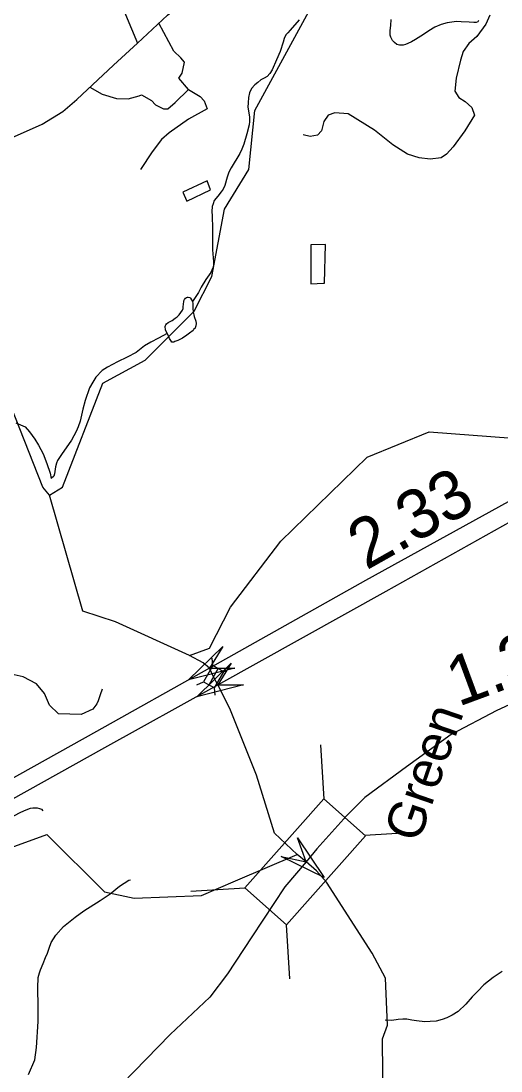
# Model space of a CAD drawing. Extents: x 2001466 to 31450019, y -30647475 to 847247.
# Drawn here: x 2190325 to 2192765, y 755901 to 761240 of the extents above; entities that cross this region are included whole.
import ezdxf

# ---------------------------------------------------------------- set-up
doc = ezdxf.new("R2010")
doc.units = 0
for name, color, linetype in [('Exist Hydrographic Creek Single Shore', 7, 'Continuous'), ('Exist Hydrographic Misc Water Feature', 7, 'Continuous'), ('Exist Road Non-System Type 51', 7, 'Continuous'), ('Exist Road Primary Interstate Structure Standard Bridge CELL', 7, 'Continuous'), ('Exist Road Primary US Divided Attributed', 7, 'Continuous'), ('Exist Road Primary US Mileage Hundredths English Label', 7, 'Continuous'), ('Exist Road Secondary Mileage Hundredths English Label', 7, 'Continuous'), ('Exist Road Secondary Structure Standard Bridge Attributed CELL', 7, 'Continuous'), ('Exist Road Secondary Structure Standard Bridge CELL', 7, 'Continuous'), ('Exist Road Secondary Type 51 Attributed', 7, 'Continuous'), ('Exist Road Secondary Type 51 Label', 7, 'Continuous')]:
    doc.layers.add(name, color=color, linetype=linetype)

msp = doc.modelspace()

# ---------------------------------------------------------------- linework, layer by layer
at = {"layer": 'Exist Hydrographic Creek Single Shore'}
for points in [[(2190469.9, 758829.2), (2190436.1, 758869.3), (2190249.9, 759342.2), (2190006.1, 759589.9), (2189744, 760189.1), (2189718.6, 760324.2), (2189687.9, 760377.7), (2189649.7, 760439.3), (2189491, 760637.1), (2189321, 761119.6), (2188915, 761967.6), (2188863.9, 762116.3), (2188570.9, 762457), (2188494, 762661.9), (2188148.9, 763220.1), (2188122.1, 763519.1), (2188062, 763651.6), (2187886, 763917.6)], [(2191181.7, 758013), (2190804.7, 758185.4), (2190639.9, 758238.5), (2190469.9, 758829.2)], [(2191729.5, 757001.5), (2191613.9, 757109.8), (2191522.8, 757405.9), (2191386.3, 757743.6), (2191325.6, 757864), (2191304.3, 757905.6), (2191282.4, 757949), (2191250.9, 757976.2), (2191181.7, 758013)], [(2185352.2, 756510.1), (2185629, 756570), (2185770.9, 756547.4), (2186303, 756582.4), (2186784.9, 756828.4), (2186910, 756829.1), (2187035.1, 756770.8), (2187169, 756646.6), (2187369.9, 756557.2), (2187911.1, 756562.5), (2188359.9, 756704.2), (2188925, 756951.8), (2189514, 757238.2), (2189606, 757229.8), (2189632.1, 757130.8), (2189775, 756855.6), (2190457, 757104.1), (2190750, 756812.6), (2190899.9, 756780), (2191241.9, 756792.7), (2191416, 756867.8), (2191729.5, 757001.5)], [(2192055.6, 754701.5), (2192091.6, 754785.1), (2192093.8, 754815.2), (2192088, 754889.1), (2192085.9, 755223.8), (2192166.9, 755533.8), (2192163, 756065.3), (2192188, 756133.7), (2192178, 756373.3), (2192109.9, 756499.4), (2191877.5, 756860.6), (2191826.2, 756918.6), (2191774.2, 756964.8), (2191729.5, 757001.5)]]:
    msp.add_lwpolyline(points, dxfattribs=at)
at = {"layer": 'Exist Hydrographic Misc Water Feature'}
for points in [[(2190469.9, 758829.2), (2190535.9, 758870.5), (2190741, 759397.7), (2190956.9, 759514.7), (2191205, 759765.4), (2191295, 759940.8), (2191359, 760283.8), (2191483.1, 760484.7), (2191514, 760785.8), (2191818.9, 761343.8), (2191840.9, 761651.7), (2192006, 762012.4), (2192146, 762206.4), (2192287.1, 762321.6), (2192478, 762406.2), (2192676.9, 762467.8), (2193190.9, 762919.7), (2193573, 763082.5), (2193722, 763181.1), (2193963, 763218.8), (2194113.1, 763284.6), (2194310.9, 763477.3), (2194694, 763604), (2194829.6, 763616.5)], [(2191181.7, 758013), (2191282.9, 758051.5), (2191390, 758259.2), (2191645.9, 758595.2), (2192083.9, 759022.4), (2192400.1, 759150.5), (2192824.9, 759118.8), (2193033.1, 759144), (2193431.9, 759355.6), (2193689, 759458.6), (2194255, 759620.8), (2194453, 759803.8), (2194794, 760000.2), (2194950.9, 760174.1), (2195089.9, 760509.1), (2195070.9, 760883.4), (2195144.9, 760967.2), (2195245, 761034), (2195426, 761276.3)], [(2191738.8, 761245.4), (2191693.2, 761193.5), (2191680.9, 761179.1), (2191671.3, 761169.2), (2191663.1, 761151), (2191657.6, 761133.1), (2191642, 761084.8), (2191624.3, 761042.9), (2191602.4, 760992.6), (2191590.5, 760972.5), (2191576.6, 760958.4), (2191560.6, 760948.6), (2191544.8, 760940.5), (2191529.2, 760928.2), (2191513.2, 760916), (2191497, 760896.2), (2191487, 760874.2), (2191481.6, 760851.9), (2191479.8, 760823.7), (2191477.5, 760801.8), (2191486.3, 760752.1), (2191485.9, 760729.9), (2191484.7, 760711.9), (2191472.8, 760666.2), (2191457.2, 760613.7), (2191447, 760587.7), (2191437.3, 760565.7), (2191393.9, 760493.5), (2191382.2, 760471.4), (2191372.3, 760445.3), (2191360.7, 760403.3), (2191352.4, 760385.4), (2191342.8, 760371), (2191324.8, 760349), (2191307.1, 760326.9), (2191301, 760310.8), (2191297.3, 760296.8), (2191295.7, 760270.7), (2191295.9, 760248.7), (2191298.3, 760185.1), (2191298.5, 760132.7), (2191299.1, 760077.1), (2191303.2, 760015.2), (2191303.4, 760000.9), (2191301.4, 759989.1), (2191295.2, 759973), (2191289.5, 759960.9), (2191263.9, 759925), (2191240.1, 759886.8), (2191226.5, 759860.4), (2191196.6, 759814.2)], [(2192650.6, 761241.9), (2192646.5, 761235.6), (2192638.7, 761232), (2192626.4, 761231.8), (2192602.4, 761233.4), (2192562.5, 761235.4), (2192538.5, 761236.9), (2192514.3, 761234.9), (2192490.7, 761230.8), (2192460.3, 761222.4), (2192428.8, 761208.5), (2192398.4, 761190), (2192370.7, 761171.8), (2192329.5, 761145.6), (2192309.2, 761133.7), (2192291.2, 761125.4), (2192279.1, 761121.2), (2192267.4, 761117.3), (2192257.5, 761117.1), (2192249.6, 761117.1), (2192241.8, 761119.1), (2192235.2, 761120.9), (2192223.3, 761130.8), (2192213.1, 761140.9), (2192205.5, 761158.7), (2192201.2, 761168.7), (2192201.2, 761178.8), (2192201, 761191), (2192204.4, 761216.8), (2192206.5, 761246.9)], [(2191288.9, 760380.8), (2191270.6, 760426.6), (2191146.8, 760369.8), (2191167.3, 760324.2), (2191288.9, 760380.8)], [(2191861.8, 759906.8), (2191867.7, 759906.7), (2191872.5, 760102.8), (2191798.2, 760102.2), (2191798, 759904.3), (2191861.8, 759906.8)], [(2191068, 759651.5), (2191059.4, 759669.5), (2191059.6, 759675.5), (2191057.8, 759681.5), (2191057.8, 759687.2), (2191059.8, 759691.3), (2191061.3, 759695.6), (2191065.4, 759699.4), (2191073.6, 759707.5), (2191093.5, 759717.5), (2191109.1, 759729.7), (2191119.5, 759735.9), (2191129.1, 759745.8), (2191137.1, 759757.9), (2191145.1, 759770.1), (2191149, 759778), (2191149, 759786.1), (2191152.9, 759814), (2191152.7, 759818), (2191156.6, 759823.9), (2191160.7, 759830.2), (2191166.5, 759834.2), (2191170.6, 759836), (2191174.5, 759836.3), (2191182.5, 759834.2), (2191186.6, 759830.4), (2191196.6, 759814.2)], [(2191196.6, 759814.2), (2191198.9, 759804.2), (2191199.1, 759780.2), (2191200.9, 759760.5), (2191205.2, 759738.3), (2191213.6, 759714.3), (2191215.5, 759702.7), (2191213.4, 759690.4), (2191211.2, 759684.6), (2191209.7, 759678.4), (2191203.6, 759672.4), (2191199.7, 759666.6), (2191181.6, 759652.2), (2191167.9, 759642.1), (2191146.2, 759628), (2191122, 759615.8), (2191106.2, 759609.7), (2191102.3, 759607.8), (2191098.2, 759607.7), (2191092.2, 759607.8), (2191086.3, 759615.5), (2191079.7, 759625.4), (2191074.2, 759639.7), (2191068, 759651.5)], [(2191068, 759651.5), (2191024, 759627.3), (2190984.2, 759607), (2190952.2, 759588.7), (2190910.8, 759554.4), (2190864.6, 759530.1), (2190815, 759507.6), (2190765.2, 759479.4), (2190737.5, 759463.3), (2190705.5, 759428.8), (2190689.5, 759402.9), (2190673.9, 759374.8), (2190650.4, 759310.6), (2190638.5, 759266.6), (2190625.1, 759204.5), (2190615.3, 759176.4), (2190605.4, 759152.3), (2190581.5, 759108.5), (2190554, 759070.1), (2190534.5, 759040.1), (2190510.5, 759006), (2190504.8, 758991.9), (2190500.5, 758973.8), (2190494.9, 758937.8), (2190491.2, 758925.8), (2190478.9, 758913.8)], [(2190299.1, 759196.6), (2190345.4, 759176.6)], [(2190345.4, 759176.6), (2190367.6, 759150.9), (2190395.7, 759113), (2190414.1, 759083), (2190438.3, 759039.2), (2190456.8, 758989.4), (2190473, 758941.5), (2190478.9, 758913.8)], [(2189622.6, 757068.1), (2189719.2, 756913.1), (2190042, 757069.3), (2190324.9, 757217.2), (2190350.8, 757229.5), (2190372.9, 757237.5), (2190384.8, 757239.7), (2190396.5, 757239.6), (2190406.7, 757239.7), (2190418.4, 757235.9), (2190428.9, 757231.9), (2190436.5, 757224.2)], [(2190363.9, 755884), (2190395.3, 755958.3), (2190403.1, 756020), (2190412.3, 756152.1), (2190411.7, 756228), (2190411.3, 756324.2), (2190412.7, 756375.9), (2190418.4, 756400.2), (2190424.4, 756416), (2190438.3, 756448.3), (2190450, 756478.2), (2190459.7, 756500.2), (2190467.4, 756526.3), (2190477.5, 756554.3), (2190501.3, 756592.5), (2190540.6, 756634.9), (2190600.7, 756683.4), (2190644.2, 756715.8), (2190727.9, 756768), (2190777.7, 756802.3), (2190825.3, 756840.9), (2190872.8, 756871.1), (2190880.8, 756873.1)], [(2192771.6, 756406.5), (2192725.7, 756376.1), (2192678.1, 756339.9), (2192646.3, 756307.4), (2192618.4, 756277.5), (2192586.9, 756240.9), (2192546.9, 756202.7), (2192517.1, 756184.5), (2192489.3, 756170.5), (2192465.3, 756162.3), (2192435.5, 756154.3), (2192405.4, 756151.9), (2192377.3, 756151.7), (2192335.5, 756155.6), (2192311.5, 756159.2), (2192285.6, 756165.1), (2192265.5, 756164.9), (2192241.6, 756162.9), (2192209.4, 756158.4), (2192175.5, 756160.3)]]:
    msp.add_lwpolyline(points, dxfattribs=at)
at = {"layer": 'Exist Road Non-System Type 51'}
for points in [[(2192707.7, 761269.1), (2192688.5, 761224.6), (2192641.6, 761161.9), (2192600.6, 761125.8), (2192573, 761084.9), (2192559.7, 761041.5), (2192537.3, 760949.5), (2192530.8, 760883.6), (2192550.5, 760850.6), (2192583.5, 760830.8), (2192616.4, 760801.1), (2192629.6, 760761.5), (2192580.2, 760682.4), (2192520.9, 760600), (2192487.9, 760563.7), (2192461.5, 760543.9), (2192405.5, 760537.3), (2192349.5, 760543.9), (2192290.2, 760563.7), (2192214.4, 760609.9), (2192122.1, 760685.7), (2191987.8, 760767.9), (2191920.4, 760772.7), (2191886.7, 760760.7), (2191865.1, 760729.4), (2191853, 760681.2), (2191831.4, 760659.5), (2191795.3, 760652.3), (2191759.2, 760661.9)], [(2191176.8, 760891.8), (2191127.3, 760950), (2191144.8, 760974.8), (2191156.4, 761030.1), (2191137.5, 761053.4), (2191102.6, 761086.9), (2191025.9, 761229)], [(2190675.3, 760903.3), (2190737.3, 760868.5), (2190810.1, 760846.7), (2190869.8, 760843.7), (2190925.1, 760859.8), (2190938.2, 760864.1), (2190987.6, 760836.5), (2191008, 760814.6), (2191049.4, 760792.9), (2191072, 760794.2), (2191108.4, 760826.3), (2191176.8, 760891.8)], [(2191176.8, 760891.8), (2191235, 760855.4), (2191256.8, 760835), (2191271.4, 760794.2), (2191176.8, 760740.4), (2191077.8, 760672.2), (2191038.6, 760637.3), (2190992, 760574.6), (2190932.3, 760484.4)], [(2190737.2, 757842.4), (2190727.2, 757813.6), (2190717.2, 757783.8), (2190710.6, 757767.3), (2190690.8, 757740.8), (2190631.2, 757714.3), (2190515.5, 757717.6), (2190469.6, 757761.9), (2190444.9, 757820.4), (2190403.9, 757869.2), (2190336.6, 757904.6), (2190259, 757922.2), (2189366.2, 757949.5), (2189169.3, 757924.6), (2189101.4, 757930)]]:
    msp.add_lwpolyline(points, dxfattribs=at)
at = {"layer": 'Exist Road Primary Interstate Structure Standard Bridge CELL'}
for p, q in [((2191300.5, 757962.4), (2191296.6, 757999.9)), ((2191280.9, 757864.3), (2191327.8, 757946.8)), ((2191354.8, 757931.5), (2191389, 757947.3)), ((2191219.2, 757864.1), (2191253.4, 757879.9)), ((2191312.2, 757811.2), (2191308.3, 757848.7))]:
    msp.add_line(p, q, dxfattribs=at)
msp.add_lwpolyline([(2191308.3, 757848.7), (2191355.3, 757931.2), (2191300.3, 757962.5), (2191253.4, 757879.9)], close=True, dxfattribs=at)
at = {"layer": 'Exist Road Primary US Divided Attributed'}
for points in [[(2196770.7, 759579.4), (2195791.4, 759623.2), (2195442.1, 759636.7), (2195106.3, 759633.3), (2194823.7, 759606.3), (2194615.3, 759577.6), (2194233.1, 759486.5), (2193825.6, 759336.2), (2193081.5, 758949.7), (2192075.8, 758394.3), (2191282.4, 757949)], [(2191325.6, 757864), (2192180.5, 758340.3), (2193155.7, 758887.2), (2193839.1, 759243.4), (2194225.5, 759385.2), (2194615.3, 759484.8), (2194971.3, 759532), (2195423.5, 759554), (2195786.3, 759538.8), (2196681.5, 759496.6)], [(2191282.4, 757949), (2190709.1, 757627.9), (2189981.8, 757222.8), (2189519.5, 756998.3), (2188917.1, 756738.3), (2188421, 756556), (2188073.4, 756439.5), (2187691.3, 756331.5), (2186877.1, 756130.6), (2186458.1, 756033.3)], [(2186407, 755923.3), (2186875.4, 756036.1), (2187730.1, 756248.7), (2188061.6, 756339.9), (2188441.3, 756463.1), (2189025.1, 756679.2), (2189585.3, 756927.4), (2190120.2, 757195.8), (2190751.3, 757545.2), (2191325.6, 757864)]]:
    msp.add_lwpolyline(points, dxfattribs=at)
at = {"layer": 'Exist Road Secondary Structure Standard Bridge Attributed CELL'}
for points in [[(2191412.4, 757948.7), (2191175.7, 757890.1), (2191351.4, 758059.2), (2191282.4, 757949)], [(2191455.6, 757864.4), (2191219.2, 757804.4), (2191394, 757974.5), (2191325.6, 757864)], [(2191730.5, 757087.2), (2191865.8, 756884.3), (2191647.2, 756992.4), (2191774.2, 756964.8)]]:
    msp.add_lwpolyline(points, close=True, dxfattribs=at)
at = {"layer": 'Exist Road Secondary Structure Standard Bridge CELL'}
for p, q in [((2191865.5, 757283.2), (2191849.1, 757558.7)), ((2192072, 757100.1), (2192347.5, 757116.5)), ((2191187.9, 756815.5), (2191463.4, 756832)), ((2191691, 756369.1), (2191674.6, 756644.6))]:
    msp.add_line(p, q, dxfattribs=at)
msp.add_lwpolyline([(2191463.4, 756832), (2191864.6, 757284.1), (2192075.8, 757096.7), (2191674.6, 756644.6)], close=True, dxfattribs=at)
at = {"layer": 'Exist Road Secondary Type 51 Attributed'}
for points in [[(2190566, 764101.9), (2190569.1, 763941.7), (2190578.5, 763779.4), (2190600, 763462.1), (2190601, 763251.6), (2190578.5, 763027.5), (2190560.8, 762815), (2190543.5, 762512.3), (2190538.3, 762338.5), (2190555.5, 762154.2), (2190581.7, 762003.4), (2190674.3, 761746.9), (2190761.1, 761510.2), (2190856.9, 761272.5), (2190916.9, 761127.3)], [(2190916.9, 761127.3), (2191070.4, 761270.5), (2191171.9, 761354.2), (2191314.7, 761444.3), (2191480, 761536.4), (2191632.8, 761613.9), (2191753.6, 761651.6), (2191907.5, 761680.9), (2192111.5, 761698.7), (2192584, 761713.4), (2193030.2, 761729.1), (2193164.2, 761737.5), (2193404.8, 761774.1), (2193827.1, 761857.9), (2194219.5, 761931.2), (2194752.6, 762040.1), (2195316.1, 762144.8), (2195671.8, 762209.7), (2196298.1, 762335.4), (2196950.5, 762482), (2197240.4, 762558.4)], [(2189687.9, 760377.7), (2189932.3, 760492.7), (2190431.9, 760715.7), (2190537.6, 760779.6), (2190608.8, 760841.4), (2190795.6, 761015.2), (2190916.9, 761127.3)], [(2194313.4, 758317.1), (2194164.8, 758259.5), (2193657.8, 758083.6), (2193013.7, 757857.4), (2192743.8, 757733.9), (2192512, 757611.4), (2192284.9, 757448), (2192072, 757290.9), (2191981, 757200.9), (2191828.4, 757030.8), (2191774.2, 756964.8)], [(2191774.2, 756964.8), (2191666.5, 756837.9), (2191498.6, 756583.1), (2191374.1, 756394.6), (2191284.1, 756276.3), (2191083.7, 756086.7), (2190838.8, 755835.4), (2190653.1, 755642.8)]]:
    msp.add_lwpolyline(points, dxfattribs=at)

# ---------------------------------------------------------------- texts
at = {"layer": 'Exist Road Primary US Mileage Hundredths English Label'}
msp.add_text('2.33', height=250, rotation=29.4753, dxfattribs=at).set_placement((2192080.3, 758445.2))
at = {"layer": 'Exist Road Secondary Mileage Hundredths English Label'}
msp.add_text('1.30', height=250, rotation=20.2727, dxfattribs=at).set_placement((2192547.5, 757752.1))
at = {"layer": 'Exist Road Secondary Type 51 Label'}
msp.add_text('Green', height=190, rotation=70.9165, dxfattribs=at).set_placement((2192346.1, 757055.3))

doc.saveas('drawing.dxf')
